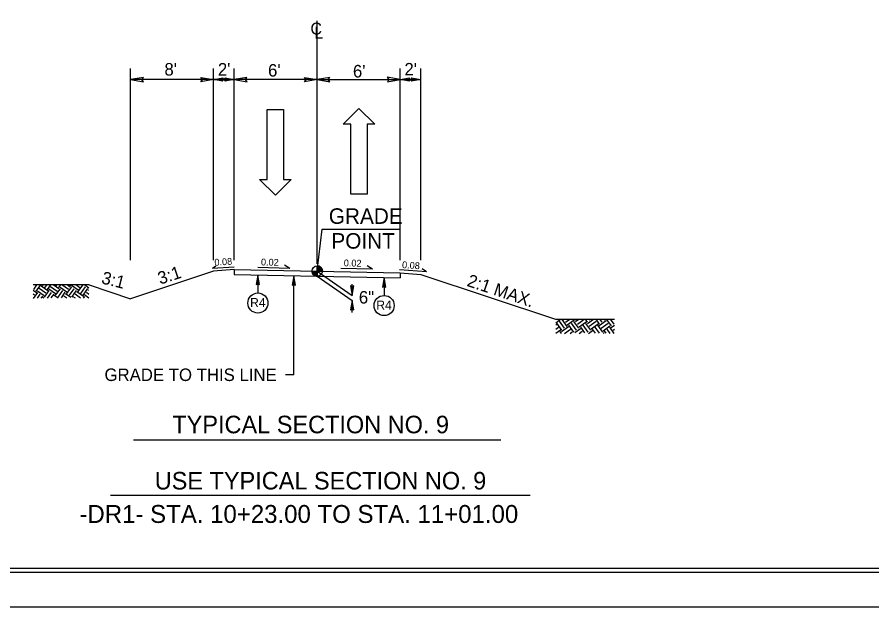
# Model space of a CAD drawing. Extents: x 3025871 to 3026431, y 707165 to 707825.
# Drawn here: x 3026095.6 to 3026178.1, y 707222.4 to 707279.4 of the extents above; entities that cross this region are included whole.
import ezdxf

# ---------------------------------------------------------------- set-up
doc = ezdxf.new("R2010")
doc.units = 0
for name, color, linetype in [('Old_Level_39', 7, 'Continuous'), ('Prop Drainage Structure Junction Box with Manhole CELL', 7, 'Continuous'), ('Prop Drainage Structure Junction Box with Manhole Label', 7, 'Continuous'), ('Prop Drainage Structure Junction Box with Slab Lid CELL', 7, 'Continuous'), ('Prop Drainage Structure Junction Box with Slab Lid TB 840 34 CELL', 7, 'Continuous'), ('Prop Drainage Structure Plot Symbol 20 Scale', 7, 'Continuous'), ('Prop Pavement Schedule Description CELL', 7, 'Continuous'), ('Sheet Cutting Line CELL', 7, 'Continuous'), ('Sheet Data Field CELL', 7, 'Continuous'), ('Sheet Sticker Incomplete CELL', 7, 'Continuous'), ('Sheet Typical CELL', 7, 'Continuous'), ('Typical Arrow Superelevation CELL', 7, 'Continuous'), ('Typical Grade Point Symbol CELL', 7, 'Continuous'), ('Typical Shoulder Slope CELL', 7, 'Continuous'), ('Typical Terminator CELL', 7, 'Continuous'), ('Typical Text Centerline CELL', 7, 'Continuous'), ('Typical Text Grade Point CELL', 7, 'Continuous')]:
    doc.layers.add(name, color=color, linetype=linetype)

msp = doc.modelspace()

# ---------------------------------------------------------------- linework, layer by layer
at = {"layer": 'Old_Level_39'}
msp.add_lwpolyline([(3026273.948, 707384.017), (3026023.973, 707384.017), (3026023.973, 707225.752), (3026273.948, 707225.752)], close=True, dxfattribs=at)
at = {"layer": 'Prop Drainage Structure Junction Box with Manhole CELL'}
msp.add_line((3026116.574, 707254.477), (3026132.573, 707254.157), dxfattribs=at)
at = {"layer": 'Prop Drainage Structure Junction Box with Manhole Label'}
msp.add_line((3026124.573, 707255.533), (3026124.573, 707278.978), dxfattribs=at)
at = {"layer": 'Prop Drainage Structure Junction Box with Slab Lid CELL'}
for p, q in [((3026124.573, 707254.82), (3026124.573, 707255.324)), ((3026124.069, 707254.82), (3026124.573, 707254.82)), ((3026124.571, 707254.317), (3026124.573, 707254.82)), ((3026124.573, 707254.82), (3026124.571, 707254.317)), ((3026125.076, 707254.82), (3026124.573, 707254.82))]:
    msp.add_line(p, q, dxfattribs=at)
for points in [[(3026124.577, 707255.324), (3026124.577, 707255.324), (3026124.577, 707254.82)], [(3026124.587, 707255.324), (3026124.587, 707254.82)], [(3026124.598, 707255.322), (3026124.597, 707254.82)], [(3026124.608, 707255.322), (3026124.607, 707254.82)], [(3026124.618, 707255.321), (3026124.617, 707254.82)], [(3026124.628, 707255.32), (3026124.628, 707254.82)], [(3026124.638, 707255.319), (3026124.638, 707254.82)], [(3026124.648, 707255.318), (3026124.648, 707254.82)], [(3026124.658, 707255.317), (3026124.658, 707254.82)], [(3026124.668, 707255.315), (3026124.668, 707254.82)], [(3026124.678, 707255.312), (3026124.678, 707254.82)], [(3026124.688, 707255.31), (3026124.688, 707254.82)], [(3026124.698, 707255.308), (3026124.698, 707254.82)], [(3026124.708, 707255.305), (3026124.708, 707254.82)], [(3026124.718, 707255.302), (3026124.718, 707254.82)], [(3026124.728, 707255.299), (3026124.728, 707254.82)], [(3026124.738, 707255.296), (3026124.738, 707254.82)], [(3026124.749, 707255.292), (3026124.748, 707254.82)], [(3026124.759, 707255.288), (3026124.758, 707254.82)], [(3026124.769, 707255.283), (3026124.769, 707254.82)], [(3026124.779, 707255.279), (3026124.779, 707254.82)], [(3026124.789, 707255.274), (3026124.789, 707254.82)], [(3026124.799, 707255.27), (3026124.799, 707254.82)], [(3026124.809, 707255.264), (3026124.809, 707254.82)], [(3026124.819, 707255.259), (3026124.819, 707254.82)], [(3026124.829, 707255.253), (3026124.829, 707254.82)], [(3026124.839, 707255.247), (3026124.839, 707254.82)], [(3026124.849, 707255.241), (3026124.849, 707254.82)], [(3026124.859, 707255.234), (3026124.859, 707254.82)], [(3026124.869, 707255.226), (3026124.869, 707254.82)], [(3026124.879, 707255.219), (3026124.879, 707254.82)], [(3026124.89, 707255.212), (3026124.889, 707254.82)], [(3026124.9, 707255.203), (3026124.899, 707254.82)], [(3026124.91, 707255.194), (3026124.909, 707254.82)], [(3026124.92, 707255.185), (3026124.92, 707254.82)], [(3026124.93, 707255.175), (3026124.93, 707254.82)], [(3026124.94, 707255.165), (3026124.94, 707254.82)], [(3026124.95, 707255.153), (3026124.95, 707254.82)], [(3026124.96, 707255.141), (3026124.96, 707254.82)], [(3026124.97, 707255.129), (3026124.97, 707254.82)], [(3026124.98, 707255.115), (3026124.98, 707254.82)], [(3026124.99, 707255.101), (3026124.99, 707254.82)], [(3026125, 707255.085), (3026125, 707254.82)], [(3026125.01, 707255.068), (3026125.01, 707254.82)], [(3026125.02, 707255.05), (3026125.02, 707254.82)], [(3026125.03, 707255.029), (3026125.03, 707254.82)], [(3026125.04, 707255.006), (3026125.04, 707254.82)], [(3026125.051, 707254.978), (3026125.051, 707254.82)], [(3026125.061, 707254.943), (3026125.061, 707254.82)], [(3026124.071, 707254.82), (3026124.071, 707254.765)], [(3026124.081, 707254.82), (3026124.081, 707254.706)], [(3026124.092, 707254.82), (3026124.091, 707254.67)], [(3026124.102, 707254.82), (3026124.102, 707254.64)], [(3026124.112, 707254.82), (3026124.112, 707254.617)], [(3026124.122, 707254.82), (3026124.122, 707254.595)], [(3026124.132, 707254.82), (3026124.132, 707254.576)], [(3026124.142, 707254.82), (3026124.142, 707254.558)], [(3026124.152, 707254.82), (3026124.152, 707254.543)], [(3026124.162, 707254.82), (3026124.162, 707254.528)], [(3026124.172, 707254.82), (3026124.172, 707254.515)], [(3026124.182, 707254.82), (3026124.182, 707254.502)], [(3026124.192, 707254.82), (3026124.192, 707254.49)], [(3026124.202, 707254.82), (3026124.202, 707254.479)], [(3026124.212, 707254.82), (3026124.212, 707254.468)], [(3026124.222, 707254.82), (3026124.222, 707254.458)], [(3026124.233, 707254.82), (3026124.232, 707254.449)], [(3026124.243, 707254.82), (3026124.242, 707254.44)], [(3026124.253, 707254.82), (3026124.253, 707254.431)], [(3026124.263, 707254.82), (3026124.263, 707254.423)], [(3026124.273, 707254.82), (3026124.273, 707254.415)], [(3026124.283, 707254.82), (3026124.283, 707254.408)], [(3026124.293, 707254.82), (3026124.293, 707254.402)], [(3026124.303, 707254.82), (3026124.303, 707254.395)], [(3026124.313, 707254.82), (3026124.313, 707254.388)], [(3026124.323, 707254.82), (3026124.323, 707254.383)], [(3026124.333, 707254.82), (3026124.333, 707254.377)], [(3026124.343, 707254.82), (3026124.343, 707254.371)], [(3026124.353, 707254.82), (3026124.353, 707254.367)], [(3026124.363, 707254.82), (3026124.363, 707254.362)], [(3026124.374, 707254.82), (3026124.373, 707254.358)], [(3026124.384, 707254.82), (3026124.383, 707254.354)], [(3026124.394, 707254.82), (3026124.393, 707254.349)], [(3026124.404, 707254.82), (3026124.404, 707254.346)], [(3026124.414, 707254.82), (3026124.414, 707254.342)], [(3026124.424, 707254.82), (3026124.424, 707254.339)], [(3026124.434, 707254.82), (3026124.434, 707254.337)], [(3026124.444, 707254.82), (3026124.444, 707254.333)], [(3026124.454, 707254.82), (3026124.454, 707254.331)], [(3026124.464, 707254.82), (3026124.464, 707254.329)], [(3026124.474, 707254.82), (3026124.474, 707254.327)], [(3026124.484, 707254.82), (3026124.484, 707254.324)], [(3026124.494, 707254.82), (3026124.494, 707254.323)], [(3026124.504, 707254.82), (3026124.504, 707254.321)], [(3026124.515, 707254.82), (3026124.514, 707254.32)], [(3026124.525, 707254.82), (3026124.524, 707254.319)], [(3026124.535, 707254.82), (3026124.534, 707254.318)], [(3026124.545, 707254.82), (3026124.545, 707254.318)], [(3026124.555, 707254.82), (3026124.555, 707254.317)], [(3026124.565, 707254.82), (3026124.565, 707254.317), (3026124.565, 707254.317)], [(3026125.071, 707254.892), (3026125.071, 707254.82)]]:
    msp.add_lwpolyline(points, dxfattribs=at)
msp.add_circle((3026124.572, 707254.82), 0.504, dxfattribs=at)
for start, end in [(359.97088, 89.97088), (179.97088, 269.97088)]:
    msp.add_arc((3026124.572, 707254.82), 0.504, start, end, dxfattribs=at)
at = {"layer": 'Prop Drainage Structure Junction Box with Slab Lid TB 840 34 CELL'}
for p, q in [((3026106.573, 707255.886), (3026106.573, 707274.383)), ((3026114.573, 707255.888), (3026114.573, 707274.385)), ((3026116.573, 707255.888), (3026116.573, 707274.385)), ((3026132.573, 707255.888), (3026132.573, 707274.385)), ((3026134.573, 707255.888), (3026134.573, 707274.385)), ((3026114.573, 707273.31), (3026106.573, 707273.31)), ((3026124.573, 707273.312), (3026114.573, 707273.312)), ((3026114.573, 707273.31), (3026116.573, 707273.312)), ((3026124.573, 707273.318), (3026134.573, 707273.318)), ((3026132.573, 707273.318), (3026134.573, 707273.32)), ((3026124.571, 707254.317), (3026127.939, 707251.981)), ((3026124.573, 707254.82), (3026127.958, 707252.471)), ((3026127.958, 707252.471), (3026127.958, 707253.564)), ((3026122.319, 707244.792), (3026121.508, 707244.792)), ((3026106.853, 707238.522), (3026142.293, 707238.522)), ((3026104.627, 707233.165), (3026145.131, 707233.165))]:
    msp.add_line(p, q, dxfattribs=at)
at = {"layer": 'Prop Drainage Structure Plot Symbol 20 Scale'}
msp.add_line((3026124.573, 707254.82), (3026125.065, 707258.856), dxfattribs=at)
at = {"layer": 'Prop Pavement Schedule Description CELL'}
for p, q in [((3026116.578, 707254.98), (3026116.575, 707254.477)), ((3026116.578, 707254.98), (3026132.573, 707254.66)), ((3026132.573, 707254.66), (3026132.573, 707254.157))]:
    msp.add_line(p, q, dxfattribs=at)
at = {"layer": 'Sheet Cutting Line CELL'}
msp.add_lwpolyline([(3026272.073, 707383.635), (3026047.073, 707383.635), (3026047.073, 707226.135), (3026272.073, 707226.135)], close=True, dxfattribs=at)
at = {"layer": 'Sheet Data Field CELL'}
for p, q in [((3026119.742, 707263.665), (3026119.742, 707270.435)), ((3026119.742, 707270.435), (3026121.337, 707270.435)), ((3026121.337, 707270.435), (3026121.337, 707263.665)), ((3026127.09, 707269.015), (3026128.589, 707270.538)), ((3026128.589, 707270.538), (3026130.136, 707269.015)), ((3026127.815, 707269.015), (3026127.09, 707269.015)), ((3026127.815, 707262.245), (3026127.815, 707269.015)), ((3026130.136, 707269.015), (3026129.411, 707269.015)), ((3026129.411, 707269.015), (3026129.411, 707262.245)), ((3026120.564, 707262.142), (3026119.016, 707263.665)), ((3026119.016, 707263.665), (3026119.742, 707263.665)), ((3026122.063, 707263.665), (3026120.564, 707262.142)), ((3026121.337, 707263.665), (3026122.063, 707263.665)), ((3026129.411, 707262.245), (3026127.815, 707262.245))]:
    msp.add_line(p, q, dxfattribs=at)
at = {"layer": 'Sheet Sticker Incomplete CELL'}
for p, q in [((3026114.462, 707255.086), (3026114.808, 707255.318)), ((3026114.462, 707255.086), (3026116.578, 707255.23)), ((3026121.921, 707255.084), (3026118.853, 707255.161)), ((3026121.921, 707255.084), (3026121.407, 707255.398)), ((3026129.909, 707254.997), (3026126.842, 707255.074)), ((3026129.909, 707254.997), (3026129.395, 707255.311)), ((3026135.132, 707254.761), (3026132.517, 707254.938)), ((3026135.132, 707254.761), (3026134.705, 707255.047))]:
    msp.add_line(p, q, dxfattribs=at)
at = {"layer": 'Sheet Typical CELL'}
for p, q in [((3026116.575, 707254.98), (3026114.575, 707254.82)), ((3026132.573, 707254.66), (3026134.573, 707254.5))]:
    msp.add_line(p, q, dxfattribs=at)
at = {"layer": 'Typical Grade Point Symbol CELL'}
for p, q in [((3026118.855, 707254.431), (3026118.855, 707252.707)), ((3026122.319, 707244.792), (3026122.314, 707254.362)), ((3026131.029, 707254.188), (3026131.029, 707252.463)), ((3026127.94, 707250.809), (3026127.939, 707251.981))]:
    msp.add_line(p, q, dxfattribs=at)
for centre in [(3026118.855, 707251.734), (3026131.029, 707251.491)]:
    msp.add_circle(centre, 0.972, dxfattribs=at)
at = {"layer": 'Typical Shoulder Slope CELL'}
msp.add_line((3026125.065, 707258.856), (3026132.478, 707258.854), dxfattribs=at)
at = {"layer": 'Typical Terminator CELL'}
msp.add_lwpolyline([(3026274.623, 707387.385), (3026022.023, 707387.385), (3026022.023, 707222.385), (3026274.623, 707222.385)], close=True, dxfattribs=at)
at = {"layer": 'Typical Text Centerline CELL'}
for points in [[(3026107.798, 707273.521), (3026106.573, 707273.31), (3026107.805, 707273.093), (3026107.648, 707273.31)], [(3026113.348, 707273.521), (3026114.573, 707273.31), (3026113.341, 707273.093), (3026113.497, 707273.31)], [(3026115.483, 707273.154), (3026114.565, 707273.312), (3026115.489, 707273.475), (3026115.371, 707273.312)], [(3026115.655, 707273.47), (3026116.573, 707273.312), (3026115.649, 707273.149), (3026115.767, 707273.312)], [(3026117.798, 707273.523), (3026116.573, 707273.312), (3026117.805, 707273.094), (3026117.648, 707273.312)], [(3026123.348, 707273.523), (3026124.573, 707273.312), (3026123.341, 707273.094), (3026123.497, 707273.312)], [(3026125.798, 707273.529), (3026124.573, 707273.318), (3026125.805, 707273.1), (3026125.648, 707273.318)], [(3026131.348, 707273.107), (3026132.573, 707273.318), (3026131.341, 707273.536), (3026131.497, 707273.318)], [(3026133.483, 707273.161), (3026132.565, 707273.32), (3026133.489, 707273.483), (3026133.371, 707273.32)], [(3026133.655, 707273.478), (3026134.573, 707273.32), (3026133.649, 707273.156), (3026133.767, 707273.32)], [(3026119.012, 707253.521), (3026118.855, 707254.431), (3026118.693, 707253.516), (3026118.855, 707253.633)], [(3026122.472, 707253.452), (3026122.314, 707254.362), (3026122.153, 707253.447), (3026122.315, 707253.563)], [(3026131.185, 707253.278), (3026131.029, 707254.188), (3026130.867, 707253.273), (3026131.029, 707253.389)], [(3026127.801, 707253.381), (3026127.958, 707252.471), (3026128.12, 707253.386), (3026127.958, 707253.27)], [(3026128.096, 707251.071), (3026127.939, 707251.981), (3026127.778, 707251.066), (3026127.939, 707251.182)]]:
    msp.add_lwpolyline(points, close=True, dxfattribs=at)
at = {"layer": 'Typical Text Grade Point CELL'}
for p, q in [((3026114.575, 707254.82), (3026106.575, 707252.153)), ((3026134.573, 707254.5), (3026147.573, 707250.167)), ((3026102.575, 707253.486), (3026097.177, 707253.486)), ((3026097.216, 707253.04), (3026097.536, 707253.486)), ((3026097.454, 707252.869), (3026097.897, 707253.486)), ((3026098.567, 707252.911), (3026097.932, 707253.368)), ((3026098.068, 707253.39), (3026098.138, 707253.486)), ((3026098.306, 707253.219), (3026098.507, 707253.498)), ((3026098.544, 707253.048), (3026098.859, 707253.486)), ((3026099.486, 707252.852), (3026098.852, 707253.308)), ((3026099.657, 707253.09), (3026099.092, 707253.496)), ((3026099.397, 707253.397), (3026099.467, 707253.495)), ((3026099.635, 707253.226), (3026099.827, 707253.494)), ((3026100.406, 707252.793), (3026099.771, 707253.249)), ((3026100.577, 707253.031), (3026099.942, 707253.487)), ((3026100.428, 707252.656), (3026100.884, 707253.291)), ((3026100.748, 707253.269), (3026100.437, 707253.492)), ((3026100.726, 707253.405), (3026100.788, 707253.491)), ((3026101.497, 707252.971), (3026100.862, 707253.427)), ((3026101.668, 707253.209), (3026101.277, 707253.49)), ((3026101.519, 707252.835), (3026101.975, 707253.469)), ((3026101.757, 707252.664), (3026102.213, 707253.298)), ((3026101.839, 707253.447), (3026101.781, 707253.488)), ((3026102.554, 707253.174), (3026102.118, 707253.487)), ((3026102.575, 707253.486), (3026106.575, 707252.153)), ((3026097.476, 707252.733), (3026097.177, 707252.947)), ((3026097.305, 707252.495), (3026097.177, 707252.587)), ((3026097.204, 707252.187), (3026097.612, 707252.755)), ((3026097.57, 707252.194), (3026097.85, 707252.584)), ((3026098.225, 707252.436), (3026097.59, 707252.892)), ((3026098.396, 707252.673), (3026097.761, 707253.13)), ((3026098.247, 707252.299), (3026098.703, 707252.934)), ((3026098.547, 707252.214), (3026098.941, 707252.763)), ((3026099.315, 707252.614), (3026098.681, 707253.07)), ((3026098.913, 707252.221), (3026099.179, 707252.592)), ((3026099.564, 707252.195), (3026099.201, 707252.455)), ((3026099.338, 707252.478), (3026099.794, 707253.112)), ((3026099.576, 707252.307), (3026100.032, 707252.941)), ((3026099.889, 707252.241), (3026100.27, 707252.77)), ((3026100.813, 707252.259), (3026100.292, 707252.634)), ((3026100.666, 707252.485), (3026101.122, 707253.12)), ((3026100.904, 707252.314), (3026101.36, 707252.949)), ((3026101.74, 707252.195), (3026101.212, 707252.575)), ((3026102.017, 707252.356), (3026101.383, 707252.813)), ((3026101.995, 707252.493), (3026102.451, 707253.127)), ((3026102.554, 707252.211), (3026102.131, 707252.515)), ((3026102.554, 707252.572), (3026102.302, 707252.753)), ((3026102.554, 707252.933), (3026102.473, 707252.991)), ((3026097.936, 707252.202), (3026098.088, 707252.413)), ((3026098.208, 707252.207), (3026098.111, 707252.277)), ((3026100.401, 707252.195), (3026100.121, 707252.396)), ((3026101.238, 707252.195), (3026101.041, 707252.337)), ((3026102.021, 707252.195), (3026102.154, 707252.379)), ((3026147.573, 707250.167), (3026153.257, 707250.167)), ((3026147.573, 707250.167), (3026153.257, 707250.167)), ((3026147.594, 707249.837), (3026148.054, 707250.168)), ((3026147.594, 707249.837), (3026148.054, 707250.168)), ((3026148.434, 707249.3), (3026147.954, 707249.969)), ((3026148.434, 707249.3), (3026147.954, 707249.969)), ((3026148.685, 707249.481), (3026148.204, 707250.149)), ((3026148.685, 707249.481), (3026148.204, 707250.149)), ((3026148.348, 707250.125), (3026148.408, 707250.169)), ((3026148.348, 707250.125), (3026148.408, 707250.169)), ((3026148.528, 707249.875), (3026148.939, 707250.17)), ((3026148.528, 707249.875), (3026148.939, 707250.17)), ((3026148.708, 707249.624), (3026149.376, 707250.104)), ((3026148.708, 707249.624), (3026149.376, 707250.104)), ((3026149.833, 707249.292), (3026149.353, 707249.961)), ((3026149.833, 707249.292), (3026149.353, 707249.961)), ((3026149.52, 707250.081), (3026149.455, 707250.172)), ((3026149.52, 707250.081), (3026149.455, 707250.172)), ((3026149.497, 707249.937), (3026149.824, 707250.173)), ((3026149.497, 707249.937), (3026149.824, 707250.173)), ((3026149.677, 707249.687), (3026150.345, 707250.167)), ((3026149.677, 707249.687), (3026150.345, 707250.167)), ((3026150.669, 707249.893), (3026150.466, 707250.175)), ((3026150.669, 707249.893), (3026150.466, 707250.175)), ((3026150.645, 707249.749), (3026151.24, 707250.177)), ((3026150.645, 707249.749), (3026151.24, 707250.177)), ((3026150.825, 707249.499), (3026151.494, 707249.979)), ((3026150.825, 707249.499), (3026151.494, 707249.979)), ((3026150.919, 707250.073), (3026150.846, 707250.176)), ((3026150.919, 707250.073), (3026150.846, 707250.176)), ((3026151.818, 707249.705), (3026151.486, 707250.167)), ((3026151.818, 707249.705), (3026151.486, 707250.167)), ((3026151.794, 707249.561), (3026152.462, 707250.042)), ((3026151.794, 707249.561), (3026152.462, 707250.042)), ((3026152.068, 707249.885), (3026151.857, 707250.179)), ((3026152.068, 707249.885), (3026151.857, 707250.179)), ((3026152.319, 707250.065), (3026152.246, 707250.167)), ((3026152.319, 707250.065), (3026152.246, 707250.167)), ((3026152.966, 707249.517), (3026152.499, 707250.167)), ((3026152.966, 707249.517), (3026152.499, 707250.167)), ((3026153.217, 707249.697), (3026152.879, 707250.167)), ((3026153.217, 707249.697), (3026152.879, 707250.167)), ((3026147.594, 707249.584), (3026147.679, 707249.645)), ((3026147.594, 707249.584), (3026147.679, 707249.645)), ((3026147.594, 707249.204), (3026147.86, 707249.394)), ((3026147.594, 707249.204), (3026147.86, 707249.394)), ((3026147.594, 707248.824), (3026148.04, 707249.144)), ((3026147.594, 707248.824), (3026148.04, 707249.144)), ((3026148.183, 707249.12), (3026147.703, 707249.789)), ((3026148.183, 707249.12), (3026147.703, 707249.789)), ((3026148.16, 707248.977), (3026148.828, 707249.457)), ((3026148.16, 707248.977), (3026148.828, 707249.457)), ((3026148.452, 707248.807), (3026149.008, 707249.206)), ((3026148.452, 707248.807), (3026149.008, 707249.206)), ((3026149.332, 707248.932), (3026148.852, 707249.601)), ((3026149.332, 707248.932), (3026148.852, 707249.601)), ((3026149.583, 707249.112), (3026149.102, 707249.781)), ((3026149.583, 707249.112), (3026149.102, 707249.781)), ((3026149.428, 707248.874), (3026149.977, 707249.269)), ((3026149.428, 707248.874), (3026149.977, 707249.269)), ((3026149.857, 707249.436), (3026150.525, 707249.916)), ((3026149.857, 707249.436), (3026150.525, 707249.916)), ((3026150.401, 707248.855), (3026150, 707249.413)), ((3026150.401, 707248.855), (3026150, 707249.413)), ((3026150.731, 707248.924), (3026150.251, 707249.593)), ((3026150.731, 707248.924), (3026150.251, 707249.593)), ((3026150.982, 707249.104), (3026150.502, 707249.773)), ((3026150.982, 707249.104), (3026150.502, 707249.773)), ((3026151.006, 707249.248), (3026151.674, 707249.728)), ((3026151.006, 707249.248), (3026151.674, 707249.728)), ((3026151.43, 707248.834), (3026151.149, 707249.224)), ((3026151.43, 707248.834), (3026151.149, 707249.224)), ((3026151.815, 707248.827), (3026151.4, 707249.405)), ((3026151.815, 707248.827), (3026151.4, 707249.405)), ((3026152.131, 707248.916), (3026151.65, 707249.585)), ((3026152.131, 707248.916), (3026151.65, 707249.585)), ((3026151.974, 707249.311), (3026152.643, 707249.791)), ((3026151.974, 707249.311), (3026152.643, 707249.791)), ((3026152.154, 707249.06), (3026152.823, 707249.54)), ((3026152.154, 707249.06), (3026152.823, 707249.54)), ((3026152.844, 707248.806), (3026152.549, 707249.217)), ((3026152.844, 707248.806), (3026152.549, 707249.217)), ((3026153.229, 707248.798), (3026152.799, 707249.397)), ((3026153.229, 707248.798), (3026152.799, 707249.397)), ((3026152.943, 707249.373), (3026153.257, 707249.599)), ((3026152.943, 707249.373), (3026153.257, 707249.599)), ((3026153.123, 707249.123), (3026153.257, 707249.219)), ((3026153.123, 707249.123), (3026153.257, 707249.219)), ((3026148.155, 707248.807), (3026148.016, 707249)), ((3026148.155, 707248.807), (3026148.016, 707249)), ((3026148.981, 707248.807), (3026149.188, 707248.956)), ((3026148.981, 707248.807), (3026149.188, 707248.956)), ((3026149.862, 707248.807), (3026150.157, 707249.018)), ((3026149.862, 707248.807), (3026150.157, 707249.018)), ((3026150.744, 707248.807), (3026151.126, 707249.081)), ((3026150.744, 707248.807), (3026151.126, 707249.081)), ((3026152.172, 707248.819), (3026152.274, 707248.893)), ((3026152.172, 707248.819), (3026152.274, 707248.893)), ((3026152.458, 707248.814), (3026152.298, 707249.036)), ((3026152.458, 707248.814), (3026152.298, 707249.036))]:
    msp.add_line(p, q, dxfattribs=at)

# ---------------------------------------------------------------- texts
at = {"layer": 'Prop Drainage Structure Junction Box with Manhole Label'}
msp.add_text('C', height=1.152, dxfattribs=at).set_placement((3026123.921, 707277.665))
msp.add_text('L', height=1.152, rotation=359.9469, dxfattribs=at).set_placement((3026124.304, 707277.272))
at = {"layer": 'Prop Drainage Structure Junction Box with Slab Lid TB 840 34 CELL'}
for s, height, p in [("8'", 1.2089, (3026109.834, 707273.703)), ("2'", 1.2089, (3026114.992, 707273.703)), ("6'", 1.2089, (3026119.834, 707273.605)), ("6'", 1.2089, (3026128.024, 707273.522)), ("2'", 1.2089, (3026132.992, 707273.711)), ('6"', 1.2089, (3026128.593, 707251.682)), ('GRADE TO THIS LINE', 1.20892, (3026104.052, 707244.202)), ('USE TYPICAL SECTION NO. 9', 1.69489, (3026108.898, 707233.727)), ('-DR1- STA. 10+23.00 TO STA. 11+01.00', 1.73151, (3026101.633, 707230.496))]:
    msp.add_text(s, height=height, dxfattribs=at).set_placement(p)
msp.add_text('TYPICAL SECTION NO. 9', height=1.69489, rotation=360, dxfattribs=at).set_placement((3026110.596, 707239.155))
at = {"layer": 'Sheet Sticker Incomplete CELL'}
for s, rotation, p in [('0.08', 3.87963, (3026114.679, 707255.328)), ('0.02', 358.5679, (3026119.143, 707255.371)), ('0.02', 358.5679, (3026127.131, 707255.284)), ('0.08', 356.12037, (3026132.746, 707255.112))]:
    msp.add_text(s, height=0.6583, rotation=rotation, dxfattribs=at).set_placement(p)
at = {"layer": 'Typical Arrow Superelevation CELL'}
for p in [(3026118.104, 707251.346), (3026130.278, 707251.103)]:
    msp.add_text('R4', height=0.87, dxfattribs=at).set_placement(p)
at = {"layer": 'Typical Shoulder Slope CELL'}
for s, p in [('GRADE', (3026125.694, 707259.383)), ('POINT', (3026125.94, 707256.987))]:
    msp.add_text(s, height=1.5, rotation=359.98041, dxfattribs=at).set_placement(p)
at = {"layer": 'Typical Text Grade Point CELL'}
for s, rotation, p in [('3:1', 17.77586, (3026109.419, 707253.509)), ('3:1', 345.96376, (3026103.683, 707253.646)), ('2:1 MAX.', 341.56505, (3026138.946, 707253.403))]:
    msp.add_text(s, height=1.2089, rotation=rotation, dxfattribs=at).set_placement(p)

doc.saveas('drawing.dxf')
